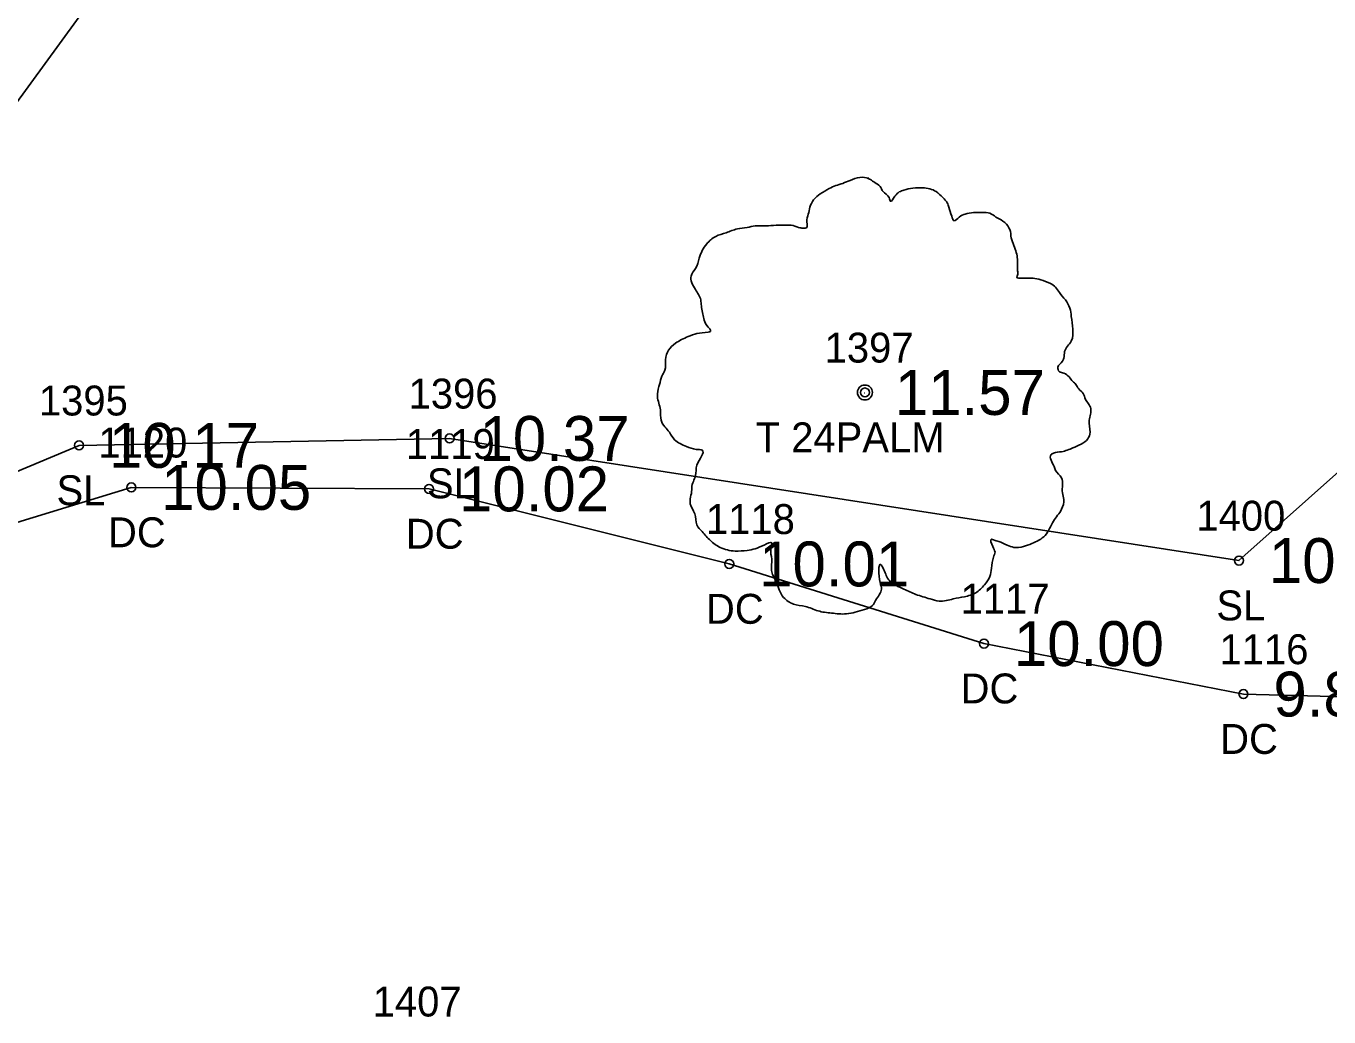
# Model space of a CAD drawing. Extents: x 2608598 to 2610682, y 641451 to 643526.
# Drawn here: x 2608849.74 to 2608893.31, y 643221.89 to 643255.02 of the extents above; entities that cross this region are included whole.
import ezdxf

# ---------------------------------------------------------------- set-up
doc = ezdxf.new("R2010")
doc.units = 0
for name, color, linetype in [('RD_EX_BldgApp_txCode', 7, 'Continuous'), ('RD_EX_Conc', 7, 'Continuous'), ('RD_EX_Conc_txCode', 7, 'Continuous'), ('RD_EX_TX_Conc_ELEV', 7, 'Continuous'), ('RD_EX_TX_VEG_ELEV', 7, 'Continuous'), ('RD_EX_VEG', 7, 'Continuous'), ('RD_EX_VEG_txCode', 7, 'Continuous'), ('RD_SMD_Locator', 7, 'Continuous')]:
    doc.layers.add(name, color=color, linetype=linetype)

msp = doc.modelspace()

# ---------------------------------------------------------------- linework, layer by layer
at = {"layer": 'RD_EX_Conc'}
msp.add_lwpolyline([(2608912.686, 643245.238), (2608903.736, 643237.982), (2608894.738, 643232.568), (2608890.456, 643232.684), (2608881.775, 643234.372), (2608873.256, 643237.035), (2608863.219, 643239.545), (2608853.257, 643239.593), (2608839.436, 643235.371), (2608836.049, 643233.556)], dxfattribs=at)
at = {"layer": 'RD_EX_VEG'}
msp.add_line((2608836.459, 643234.694), (2608866.889, 643276.419), dxfattribs=at)
msp.add_lwpolyline([(2608836.459, 643234.694), (2608851.513, 643240.999), (2608863.902, 643241.231), (2608890.306, 643237.148), (2608905.295, 643250.492), (2608879.955, 643271.747), (2608872.023, 643277.245), (2608866.889, 643276.419)], dxfattribs=at)
for centre, radius in [((2608877.794, 643242.768), 0.25), ((2608877.781, 643242.749), 0.0001)]:
    msp.add_circle(centre, radius, dxfattribs=at)
for points in [[(2608877.926, 643249.935), (2608877.626, 643249.96), (2608877.301, 643249.86), (2608877.051, 643249.76), (2608876.826, 643249.685), (2608876.601, 643249.585), (2608876.302, 643249.41), (2608876.077, 643249.21), (2608875.952, 643248.96), (2608875.902, 643248.735), (2608875.852, 643248.461), (2608875.852, 643248.286), (2608875.727, 643248.261), (2608875.577, 643248.286), (2608875.327, 643248.361), (2608875.077, 643248.361), (2608874.827, 643248.361), (2608874.477, 643248.336), (2608874.127, 643248.336), (2608873.853, 643248.286), (2608873.528, 643248.236), (2608873.153, 643248.111), (2608872.803, 643247.986), (2608872.503, 643247.736), (2608872.253, 643247.261), (2608872.128, 643246.911), (2608871.978, 643246.661), (2608872.128, 643246.212), (2608872.303, 643245.862), (2608872.328, 643245.662), (2608872.403, 643245.237), (2608872.503, 643245.012), (2608872.628, 643244.812), (2608872.553, 643244.787), (2608872.178, 643244.737), (2608871.878, 643244.637), (2608871.454, 643244.412), (2608871.229, 643244.187), (2608871.129, 643243.863), (2608871.104, 643243.513), (2608871.004, 643243.313), (2608870.929, 643243.038), (2608870.904, 643242.963), (2608870.854, 643242.638), (2608870.954, 643242.188), (2608870.979, 643241.838), (2608871.104, 643241.614), (2608871.254, 643241.439), (2608871.429, 643241.189), (2608871.828, 643240.964), (2608872.153, 643240.864), (2608872.353, 643240.839), (2608872.178, 643240.339), (2608872.128, 643239.989), (2608872.003, 643239.589), (2608872.003, 643239.515), (2608871.953, 643239.04), (2608872.103, 643238.715), (2608872.178, 643238.34), (2608872.353, 643238.115), (2608872.628, 643237.815), (2608872.953, 643237.59), (2608873.453, 643237.465), (2608873.853, 643237.49), (2608874.427, 643237.665), (2608874.677, 643237.74), (2608874.652, 643237.565), (2608874.677, 643237.19), (2608874.677, 643236.766), (2608874.827, 643236.441), (2608874.927, 643236.166), (2608875.077, 643235.916), (2608875.402, 643235.691), (2608875.802, 643235.616), (2608876.227, 643235.466), (2608876.676, 643235.391), (2608877.176, 643235.366), (2608877.776, 643235.516), (2608878.051, 643235.641), (2608878.151, 643235.816), (2608878.351, 643236.191), (2608878.301, 643236.416), (2608878.326, 643237.016), (2608878.426, 643236.841), (2608878.601, 643236.491), (2608879.1, 643236.191), (2608879.5, 643236.016), (2608879.975, 643235.866), (2608880.275, 643235.791), (2608880.75, 643235.866), (2608881.124, 643235.941), (2608881.499, 643236.066), (2608881.799, 643236.341), (2608881.974, 643236.616), (2608882.024, 643236.891), (2608882.099, 643237.265), (2608882.149, 643237.44)], [(2608882.149, 643237.44), (2608882.074, 643237.615), (2608882.024, 643237.865), (2608882.099, 643237.84), (2608882.274, 643237.79), (2608882.549, 643237.665), (2608882.774, 643237.59), (2608883.099, 643237.615), (2608883.373, 643237.715), (2608883.823, 643237.99), (2608884.098, 643238.465), (2608884.373, 643238.865), (2608884.448, 643239.19), (2608884.398, 643239.415), (2608884.373, 643239.914), (2608884.173, 643240.164), (2608884.123, 643240.289), (2608884.023, 643240.689), (2608884.098, 643240.739), (2608884.373, 643240.789), (2608884.748, 643240.914), (2608885.023, 643241.039), (2608885.248, 643241.214), (2608885.323, 643241.439), (2608885.298, 643241.838), (2608885.348, 643242.238), (2608885.273, 643242.388), (2608885.173, 643242.538), (2608885.098, 643242.738), (2608884.948, 643242.888), (2608884.848, 643243.038), (2608884.748, 643243.138), (2608884.623, 643243.288), (2608884.448, 643243.413), (2608884.298, 643243.463), (2608884.248, 643243.613), (2608884.398, 643243.813), (2608884.448, 643243.913), (2608884.473, 643244.137), (2608884.698, 643244.487), (2608884.748, 643244.887), (2608884.698, 643245.312), (2608884.648, 643245.587), (2608884.498, 643245.862), (2608884.298, 643246.112), (2608884.173, 643246.287), (2608883.998, 643246.411), (2608883.673, 643246.536), (2608883.423, 643246.586), (2608883.074, 643246.586), (2608882.874, 643246.636), (2608882.899, 643246.686), (2608882.899, 643246.836), (2608882.899, 643247.111), (2608882.824, 643247.561), (2608882.674, 643248.061), (2608882.674, 643248.086), (2608882.574, 643248.336), (2608882.349, 643248.536), (2608882.174, 643248.635), (2608881.974, 643248.76), (2608881.724, 643248.785), (2608881.424, 643248.785), (2608881.149, 643248.735), (2608880.949, 643248.635), (2608880.775, 643248.511), (2608880.7, 643248.66), (2608880.6, 643248.96), (2608880.55, 643249.11), (2608880.4, 643249.285), (2608880.175, 643249.485), (2608879.725, 643249.61), (2608879.1, 643249.535), (2608878.8, 643249.335), (2608878.65, 643249.16), (2608878.601, 643249.285), (2608878.401, 643249.485), (2608878.301, 643249.66), (2608878.126, 643249.785), (2608877.976, 643249.885), (2608877.876, 643249.935)]]:
    msp.add_spline(points, degree=3, dxfattribs=at)
at = {"layer": 'RD_SMD_Locator'}
for centre in [(2608877.794, 643242.768), (2608863.902, 643241.231), (2608851.513, 643240.999), (2608853.257, 643239.593), (2608863.219, 643239.545), (2608873.256, 643237.035), (2608890.306, 643237.148), (2608881.775, 643234.372), (2608890.456, 643232.684)]:
    msp.add_circle(centre, 0.15, dxfattribs=at)

# ---------------------------------------------------------------- texts
at = {"layer": 'RD_EX_BldgApp_txCode'}
msp.add_text('1407', height=1, dxfattribs=at).set_placement((2608861.331, 643221.904))
at = {"layer": 'RD_EX_Conc_txCode'}
for s, p in [('1120', (2608852.155, 643240.593)), ('1119', (2608862.44, 643240.545)), ('1118', (2608872.477, 643238.035)), ('DC', (2608852.478, 643237.593)), ('DC', (2608862.44, 643237.545)), ('1117', (2608880.995, 643235.372)), ('DC', (2608872.477, 643235.035)), ('1116', (2608889.653, 643233.684)), ('DC', (2608880.995, 643232.372)), ('DC', (2608889.676, 643230.684))]:
    msp.add_text(s, height=1, dxfattribs=at).set_placement(p)
at = {"layer": 'RD_EX_TX_Conc_ELEV'}
for s, p in [('10.05', (2608854.257, 643238.843)), ('10.02', (2608864.219, 643238.795)), ('10.01', (2608874.256, 643236.285)), ('10.00', (2608882.775, 643233.622)), ('9.87', (2608891.456, 643231.934))]:
    msp.add_text(s, height=1.5, dxfattribs=at).set_placement(p)
at = {"layer": 'RD_EX_TX_VEG_ELEV'}
for s, p in [('11.57', (2608878.794, 643242.018)), ('10.17', (2608852.513, 643240.249)), ('10.37', (2608864.902, 643240.481)), ('10.67', (2608891.306, 643236.398))]:
    msp.add_text(s, height=1.5, dxfattribs=at).set_placement(p)
at = {"layer": 'RD_EX_VEG_txCode'}
for s, p in [('1397', (2608876.447, 643243.768)), ('1396', (2608862.532, 643242.231)), ('1395', (2608850.167, 643241.999)), ('T 24PALM', (2608874.14, 643240.768)), ('SL', (2608850.757, 643238.999)), ('SL', (2608863.146, 643239.231)), ('1400', (2608888.881, 643238.148)), ('SL', (2608889.55, 643235.148))]:
    msp.add_text(s, height=1, dxfattribs=at).set_placement(p)

doc.saveas('drawing.dxf')
